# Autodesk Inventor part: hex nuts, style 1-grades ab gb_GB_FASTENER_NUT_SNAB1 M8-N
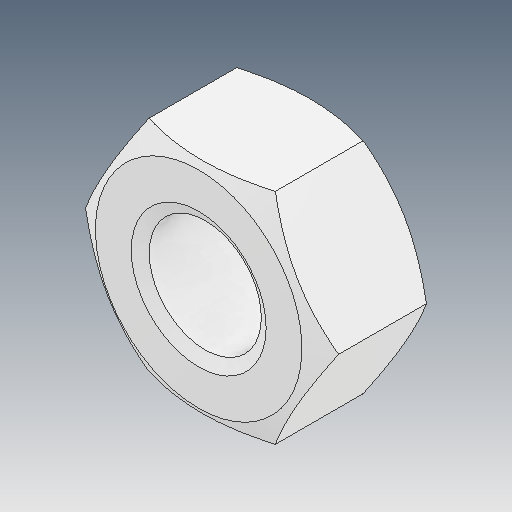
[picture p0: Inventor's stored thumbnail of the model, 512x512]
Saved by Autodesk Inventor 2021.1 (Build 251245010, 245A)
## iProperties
Created: 2021-05
Part Number: hex nuts, style 1-grades ab gb_GB_FASTENER_NUT_SNAB1 M8-N
Material: Ogólny
Document SubType Name: Modeling
Designer: user
Density: 1 g/cm^3
Appearance: Domyślna
Author: user
Revision Number: ÈÎºÎ
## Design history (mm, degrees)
feature "ÊäÈë1"
node "Bryła1"
